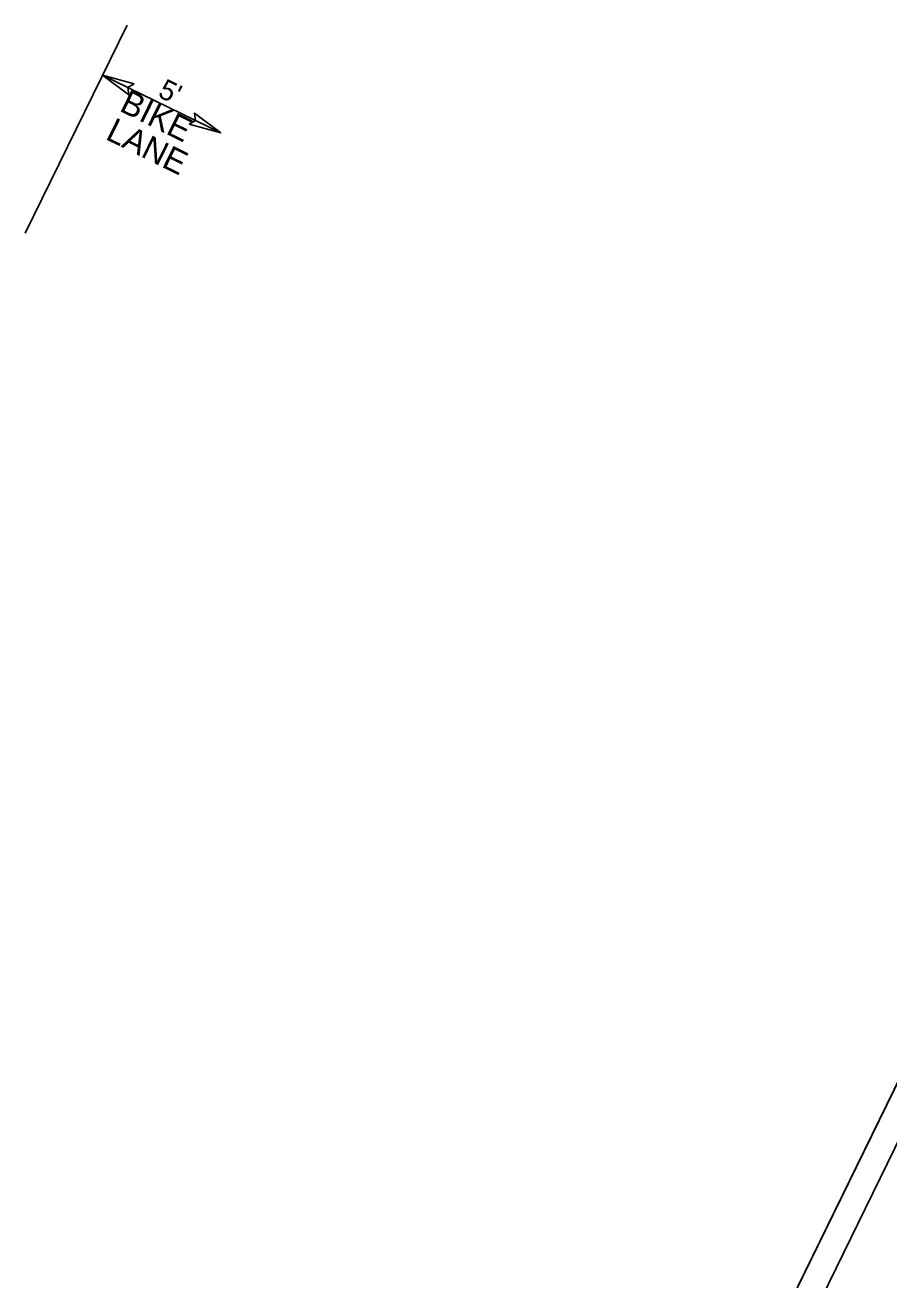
# Model space of a CAD drawing. Extents: x 1518247 to 1523638, y 635234 to 639927.
# Drawn here: x 1519826 to 1520253, y 637475 to 638094 of the extents above; entities that cross this region are included whole.
import ezdxf

# ---------------------------------------------------------------- set-up
doc = ezdxf.new("R2010")
doc.units = 0
for name, color, linetype in [('Default', 7, 'Continuous'), ('Prop Dimension', 7, 'Continuous'), ('Prop Shade Light', 7, 'Continuous'), ('Sheet Cutting Line CELL', 7, 'Continuous'), ('Sheet Plot Border Inside CELL', 7, 'Continuous'), ('Sheet Plot Border Outside CELL', 7, 'Continuous')]:
    doc.layers.add(name, color=color, linetype=linetype)

# ---------------------------------------------------------------- blocks, each defined once
blk = doc.blocks.new('TERMINATOR')
at = {"layer": 'Prop Shade Light'}
blk.add_lwpolyline([(-0.469, 0.081), (0, 0), (-0.471, -0.083), (-0.411, 0)], close=True, dxfattribs=at)

msp = doc.modelspace()

# ---------------------------------------------------------------- linework, layer by layer
at = {"layer": 'Default'}
msp.add_lwpolyline([(1521471.45, 636222.33), (1519958.68, 636962.19), (1520441.97, 637950.34), (1521954.73, 637210.48)], close=True, dxfattribs=at)
at = {"layer": 'Prop Dimension'}
for p, q in [((1519826.14, 637991.03), (1519876.49, 638093.79)), ((1519864.37, 638069.05), (1519922.75, 638040.56))]:
    msp.add_line(p, q, dxfattribs=at)
at = {"layer": 'Sheet Cutting Line CELL'}
msp.add_line((1520441.97, 637950.34), (1519958.68, 636962.19), dxfattribs=at)
at = {"layer": 'Sheet Plot Border Inside CELL'}
msp.add_lwpolyline([(1521940.83, 637192.29), (1520443.78, 637924.46), (1519980.23, 636976.65), (1521477.27, 636244.48)], close=True, dxfattribs=at)
at = {"layer": 'Sheet Plot Border Outside CELL'}
msp.add_lwpolyline([(1521954.73, 637210.48), (1520441.97, 637950.34), (1519958.68, 636962.19), (1521471.45, 636222.33)], close=True, dxfattribs=at)

# ---------------------------------------------------------------- block references
at = {"layer": 'Prop Dimension', "xscale": 33.82820784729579, "yscale": -36.41552511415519}
for p, rotation in [((1519864.37, 638069.05), 153.97926941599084), ((1519922.75, 638040.56), -26.020730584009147)]:
    msp.add_blockref('TERMINATOR', p, dxfattribs=dict(at, rotation=rotation))

# ---------------------------------------------------------------- texts
at = {"layer": 'Prop Dimension'}
for s, height, rotation, p in [('BIKE', 11.865, 333.74084, (1519872.18, 638051.68)), ("5'", 9.969, 333.97927, (1519891.2, 638058.65)), ('LANE', 11.865, 333.74084, (1519865.3, 638037.73))]:
    msp.add_text(s, height=height, rotation=rotation, dxfattribs=at).set_placement(p)

doc.saveas('drawing.dxf')
